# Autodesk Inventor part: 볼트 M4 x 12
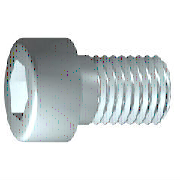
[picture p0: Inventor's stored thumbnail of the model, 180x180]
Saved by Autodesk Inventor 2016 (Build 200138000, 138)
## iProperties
IsCustomPart: 0
Created: 2012-02
Part Number: 볼트 M4 x 12
Material: 스테인리스강
Description: 6각 소켓 머리 캡 나사
Document SubType Name: Modeling
Standard: ISO 4762
Designer: mduedu
Standard Revision: Fourth edition 2004-03-01
Standards Organization: ISO
Language: ko-KR
Size Designation: M4 x 12
Categories: <MemberInstance><Categories><Category DisplayName="조임쇠" InternalName="e4da775c-781d-43d5-af7c-5136215cf5a6" Mnemonic="FSTN"><Category DisplayName="볼트" InternalN
Density: 8.08 g/cm^3
Mass: 2.29719 g
Surface Area: 3.30853 cm^2
Volume: 0.284306 cm^3
Appearance: 반광택
Author: mduedu
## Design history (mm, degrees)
sketch "스케치1"
  geometry: L1 (-1, 0)-(12, 0); L2 (12, 0)-(12, 2); L3 (12, 2)-(1.75, 2); L4 (1.75, 2)-(1.32, 2); L5 (1.32, 2)-(0, 2); L6 (0, 2)-(0, 3.5); L7 (0, 3.5)-(-4, 3.5); L8 (-4, 3.5)-(-4, 1.732); L9 (-4, 1.732)-(-2, 1.732); L10 (-2, 1.732)-(-1, 0); L11 (-7.2, 0)-(15.2, 0) reference; L12 (0, -0.7)-(0, 4.2) reference; L13 (1.75, 2)-(0, 2)
  constraints: 22 end point, 6 parallel, 2 collinear, 2 perpendicular, 1 horizontal, 1 point on line
  dimensions: "d1" = 10.25 distance from line of L3.end L2 (= GEL); "d2" = 0.42952 distance of L4.end L3.end (computed from GAL); "d3" = 4 distance between parallel lines of L8 L6 (= KOH); "d4" = 2 distance of L8.end L9.end (= INTI); "d5" = 60 deg angle of L10 L1; "d6" = 4 diameter of L3 L1 (= GD); "d7" = 4 diameter of L5 L1 (= BDM); "d8" = 3.4641 diameter of L9 L1 (= 1.1547 x SW); "d9" = 7 diameter of L7 L1 (= KOD); "d26" = 12 distance between parallel lines of L12 L2 (= NLG)
revolve "본체" sketch "스케치1" stored, may be unused: angle "d10" = 90 deg
sketch "스케치2"
  geometry: L1 (0, -4.9)-(0, 4.9) reference; L2 (-4.9, 0)-(4.9, 0) reference; L3 (1.732, 0)-(0.866, -1.5); L4 (0.866, -1.5)-(-0.866, -1.5); L5 (-0.866, -1.5)-(-1.732, 0); L6 (-1.732, 0)-(-0.866, 1.5); L7 (-0.866, 1.5)-(0.866, 1.5); L8 (0.866, 1.5)-(1.732, 0); 2 further points
  constraints: 12 end point, 1 coincident, 1 horizontal alignment, 1 point on line, 12 other
extrude "슬롯" join sketch "스케치2" stored distance "d11" = 10; taper "d12" = 0 deg
workplane "Work Plane1"
fillet "Fillet2" dims "d30" = 0.1 (= R)
body "Solid1"
fillet "모깎기1" dims "d17" = 0.4 (= RR)
feature "스레드" dims "d13" = 10.25 (= GEL), "d14" = 0
chamfer "모따기1" distance "d15" = 0.42941 (= -0.5 x SPD + 0.5 x GD); stored, may be unused: second distance "d16" = 0.42941 (= GUL), angle "d27" = 45 deg
other parameters: "GD" = 4 [user parameter; used in 2 equation terms], "NLG" = 12 [user parameter; used in 1 equation term], "GEL" = 10.25 [user parameter; used in 2 equation terms], "KOD" = 7 [user parameter; used in 1 equation term], "KOH" = 4 [user parameter; used in 1 equation term], "INTI" = 2 [user parameter; used in 1 equation term], "GAL" = 0.42941 (= 0.61345 x PTC) [user parameter; used in 1 equation term], "GUL" = 0.42941 (= 0.61345 x PTC) [user parameter; used in 1 equation term], "BDM" = 4 (= NND) [user parameter; used in 1 equation term], "SW" = 3 [user parameter; used in 2 equation terms], "RR" = 0.4 [user parameter; used in 1 equation term], "SPD" = 3.14117 (= NND - 1.2269 x PTC) [user parameter; used in 1 equation term], "d19" = 0, "d28" = 0, "d29" = 0, "R" = 0.1 [user parameter; used in 1 equation term], "TOA" = 30 deg [user parameter], "GD1" = 3.14117 (= THREADDIA - 1.2269 x PTC) [user parameter], "THREADDIA" = 4 [user parameter; used in 1 equation term], "FAWI" = 45 deg [user parameter], "TPU" = 14.28571 (computed from PTC) [user parameter], "PTC" = 0.7 [user parameter; used in 5 equation terms], "NND" = 4 [user parameter; used in 2 equation terms], "E0" = 3.465 (= 1.155 x SW) [user parameter]
